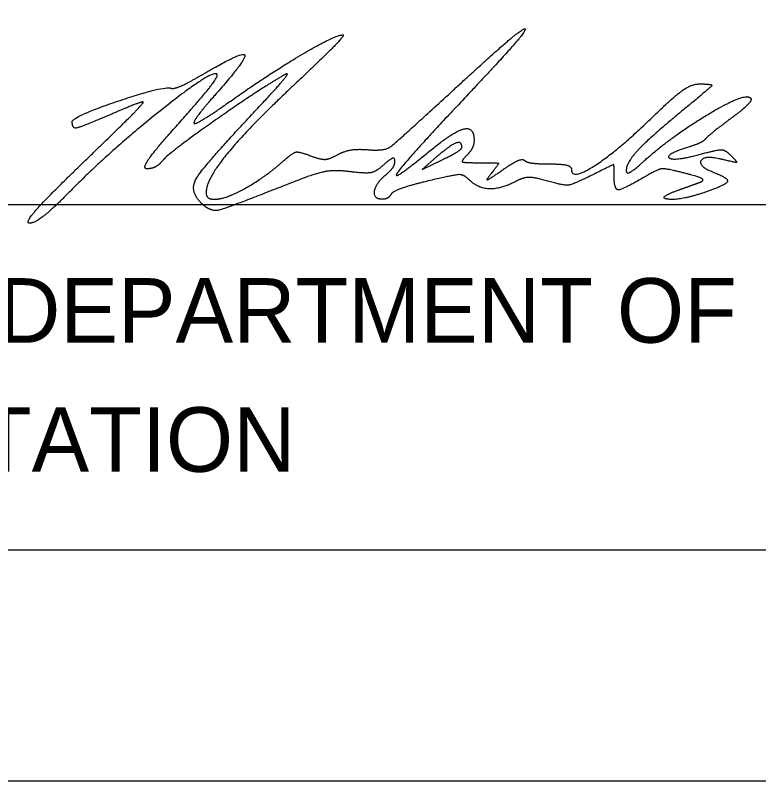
# Model space of a CAD drawing. Extents: x 0 to 2329303, y 0 to 694397.
# Drawn here: x 27.744 to 29.356, y 0 to 1.66 of the extents above; entities that cross this region are included whole.
import ezdxf

# ---------------------------------------------------------------- set-up
doc = ezdxf.new("R2010")
doc.units = 0
for name, color, linetype in [('SH_Border', 7, 'Continuous'), ('SH_Cut_Line', 7, 'Continuous'), ('SH_Data', 7, 'Continuous'), ('SH_Text', 7, 'Continuous')]:
    doc.layers.add(name, color=color, linetype=linetype)

msp = doc.modelspace()

# ---------------------------------------------------------------- linework, layer by layer
at = {"layer": 'SH_Border'}
msp.add_lwpolyline([(1.5, 21.5), (33.5, 21.5), (33.5, 0.5), (1.5, 0.5)], close=True, dxfattribs=at)
at = {"layer": 'SH_Cut_Line'}
msp.add_lwpolyline([(0, 0), (34, 0), (34, 22), (0, 22)], close=True, dxfattribs=at)
at = {"layer": 'SH_Data'}
msp.add_line((26.625, 1.25), (31.5, 1.25), dxfattribs=at)
at = {"layer": 'SH_Text'}
for p, q in [((28.7123, 1.3738), (28.7123, 1.3738)), ((27.8916, 1.341), (27.8916, 1.341))]:
    msp.add_line(p, q, dxfattribs=at)
msp.add_lwpolyline([(28.6576, 1.353), (28.6265, 1.3259), (28.6694, 1.3467)], dxfattribs=at)
for points in [[(28.6937, 1.4978), (28.7729, 1.5708), (28.8426, 1.6306), (28.8487, 1.6307)], [(28.8487, 1.6307), (28.8547, 1.6307), (28.7998, 1.5672), (28.7266, 1.4895)], [(28.214, 1.4763), (28.299, 1.5361), (28.4377, 1.6176), (28.4543, 1.6176)], [(28.4543, 1.6176), (28.4594, 1.6176), (28.4158, 1.5726), (28.3574, 1.5176)], [(28.1517, 1.5328), (28.2349, 1.5815), (28.2478, 1.5675), (28.1853, 1.4965)], [(28.1814, 1.5325), (28.1712, 1.5427), (27.9497, 1.3664), (27.8675, 1.2827)], [(28.3295, 1.532), (28.2777, 1.5027), (28.0788, 1.3631), (28.0648, 1.3462)], [(28.0824, 1.5019), (28.0883, 1.5), (28.1195, 1.5139), (28.1517, 1.5328)], [(28.0992, 1.4265), (28.1481, 1.4811), (28.1851, 1.5288), (28.1814, 1.5325)], [(28.2606, 1.4487), (28.3094, 1.5007), (28.3404, 1.5382), (28.3295, 1.532)], [(28.3574, 1.5176), (28.2521, 1.4186), (28.1579, 1.3044), (28.1579, 1.2759)], [(29.1248, 1.4384), (29.1725, 1.4847), (29.2117, 1.5118), (29.2304, 1.5114)], [(29.2304, 1.5114), (29.2561, 1.5109), (29.252, 1.5042), (29.2007, 1.4619)], [(27.8677, 1.4295), (27.8679, 1.4406), (28.0658, 1.5074), (28.0824, 1.5019)], [(28.1853, 1.4965), (28.1557, 1.4629), (28.1315, 1.4315), (28.1315, 1.4268)], [(28.5089, 1.3686), (28.5442, 1.3656), (28.569, 1.383), (28.6937, 1.4978)], [(28.7266, 1.4895), (28.5898, 1.3443), (28.5559, 1.2943), (28.6427, 1.3659)], [(29.105, 1.3421), (29.1616, 1.3937), (29.3168, 1.4887), (29.3346, 1.4828)], [(29.3346, 1.4828), (29.3435, 1.4798), (29.3274, 1.46), (29.2988, 1.4387)], [(27.8916, 1.341), (27.9666, 1.4133), (28.025, 1.4724), (28.0214, 1.4724)], [(28.0214, 1.4724), (28.0178, 1.4724), (27.9872, 1.4605), (27.9533, 1.446)], [(28.1315, 1.4268), (28.1315, 1.4221), (28.1686, 1.4444), (28.214, 1.4763)], [(29.2007, 1.4619), (29.1225, 1.3976), (29.0687, 1.3411), (29.0687, 1.3234)], [(27.9533, 1.446), (27.8872, 1.4177), (27.8674, 1.4139), (27.8677, 1.4295)], [(28.1476, 1.2527), (28.121, 1.2793), (28.1515, 1.3322), (28.2606, 1.4487)], [(28.9499, 1.3256), (28.9499, 1.3015), (29.0505, 1.3664), (29.1248, 1.4384)], [(29.2988, 1.4387), (29.2702, 1.4174), (29.2439, 1.3963), (29.2403, 1.3918)], [(28.0297, 1.3272), (28.0188, 1.3272), (28.0493, 1.3708), (28.0992, 1.4265)], [(28.6427, 1.3659), (28.6938, 1.408), (28.7387, 1.4189), (28.7387, 1.3893)], [(28.7123, 1.3738), (28.7123, 1.388), (28.6868, 1.3783), (28.6576, 1.353)], [(28.7387, 1.3893), (28.7387, 1.3798), (28.7315, 1.365), (28.7228, 1.3563)], [(29.2403, 1.3918), (29.2366, 1.3873), (29.2203, 1.3794), (29.204, 1.3743)], [(28.3242, 1.3431), (28.3456, 1.3621), (28.3592, 1.3649), (28.3843, 1.3554)], [(28.4424, 1.3575), (28.4565, 1.3655), (28.4864, 1.3705), (28.5089, 1.3686)], [(28.6694, 1.3467), (28.693, 1.3581), (28.7123, 1.3703), (28.7123, 1.3738)], [(29.204, 1.3743), (29.1517, 1.358), (29.1723, 1.3435), (29.227, 1.3582)], [(29.227, 1.3582), (29.2675, 1.369), (29.2836, 1.3683), (29.2963, 1.3554)], [(28.0648, 1.3462), (28.0561, 1.3358), (28.0403, 1.3272), (28.0297, 1.3272)], [(28.3843, 1.3554), (28.4056, 1.3473), (28.4254, 1.348), (28.4424, 1.3575)], [(28.5671, 1.3441), (28.5671, 1.3516), (28.5564, 1.348), (28.5432, 1.3361)], [(28.7228, 1.3563), (28.7105, 1.3439), (28.7167, 1.3404), (28.7509, 1.3404)], [(28.7996, 1.324), (28.8222, 1.3399), (28.844, 1.3494), (28.8482, 1.3453)], [(28.8482, 1.3453), (28.8523, 1.3412), (28.8769, 1.3378), (28.9028, 1.3378)], [(29.2766, 1.3475), (29.2378, 1.3571), (29.2238, 1.3327), (29.2601, 1.3188)], [(29.2963, 1.3554), (29.3097, 1.3418), (29.3059, 1.3403), (29.2766, 1.3475)], [(27.7751, 1.2092), (27.7642, 1.2094), (27.8166, 1.2687), (27.8916, 1.341)], [(28.1769, 1.2612), (28.1999, 1.2612), (28.2858, 1.309), (28.3242, 1.3431)], [(28.5432, 1.3361), (28.5267, 1.3212), (28.5043, 1.3165), (28.4698, 1.3209)], [(28.5473, 1.314), (28.5582, 1.3231), (28.5671, 1.3366), (28.5671, 1.3441)], [(28.7509, 1.3404), (28.7905, 1.3404), (28.793, 1.3382), (28.7766, 1.3178)], [(28.9028, 1.3378), (28.9287, 1.3378), (28.9499, 1.3323), (28.9499, 1.3256)], [(29.0423, 1.3124), (29.0423, 1.3365), (29.0411, 1.3365), (28.9924, 1.3124)], [(29.0687, 1.3234), (29.0687, 1.3155), (29.085, 1.3239), (29.105, 1.3421)], [(28.4698, 1.3209), (28.439, 1.3249), (28.3969, 1.318), (28.3584, 1.3028)], [(28.5399, 1.2612), (28.5205, 1.2612), (28.5253, 1.2958), (28.5473, 1.314)], [(28.7285, 1.303), (28.7168, 1.3148), (28.6956, 1.3142), (28.6395, 1.3008)], [(28.7766, 1.3178), (28.7639, 1.302), (28.7708, 1.3038), (28.7996, 1.324)], [(28.9924, 1.3124), (28.9529, 1.2929), (28.9334, 1.2904), (28.8983, 1.3005)], [(29.1077, 1.3092), (29.0601, 1.2811), (29.0423, 1.2819), (29.0423, 1.3124)], [(29.1955, 1.3176), (29.1545, 1.3281), (29.1368, 1.3264), (29.1077, 1.3092)], [(29.2271, 1.2974), (29.2391, 1.3017), (29.2267, 1.3097), (29.1955, 1.3176)], [(29.2601, 1.3188), (29.2923, 1.3064), (29.2829, 1.2907), (29.2336, 1.2744)], [(28.3584, 1.3028), (28.2041, 1.2419), (28.1671, 1.2331), (28.1476, 1.2527)], [(28.6395, 1.3008), (28.599, 1.2911), (28.5628, 1.2782), (28.5591, 1.2722)], [(28.8303, 1.3004), (28.7978, 1.283), (28.7473, 1.2843), (28.7285, 1.303)], [(28.8983, 1.3005), (28.87, 1.3086), (28.8456, 1.3086), (28.8303, 1.3004)], [(29.1809, 1.2807), (29.1954, 1.2859), (29.2162, 1.2934), (29.2271, 1.2974)], [(27.8675, 1.2827), (27.8275, 1.242), (27.786, 1.209), (27.7751, 1.2092)], [(29.2336, 1.2744), (29.1844, 1.2581), (29.1344, 1.2642), (29.1809, 1.2807)], [(28.1579, 1.2759), (28.1579, 1.2678), (28.1664, 1.2612), (28.1769, 1.2612)], [(28.5591, 1.2722), (28.5554, 1.2661), (28.5467, 1.2612), (28.5399, 1.2612)]]:
    msp.add_open_spline(points, degree=2, dxfattribs=at)

# ---------------------------------------------------------------- texts
at = {"layer": 'SH_Data'}
for s, p in [('DIRECTOR, DEPARTMENT OF', (26.625, 0.95)), ('TRANSPORTATION', (26.625, 0.67))]:
    msp.add_text(s, height=0.14, dxfattribs=at).set_placement(p)

doc.saveas('drawing.dxf')
